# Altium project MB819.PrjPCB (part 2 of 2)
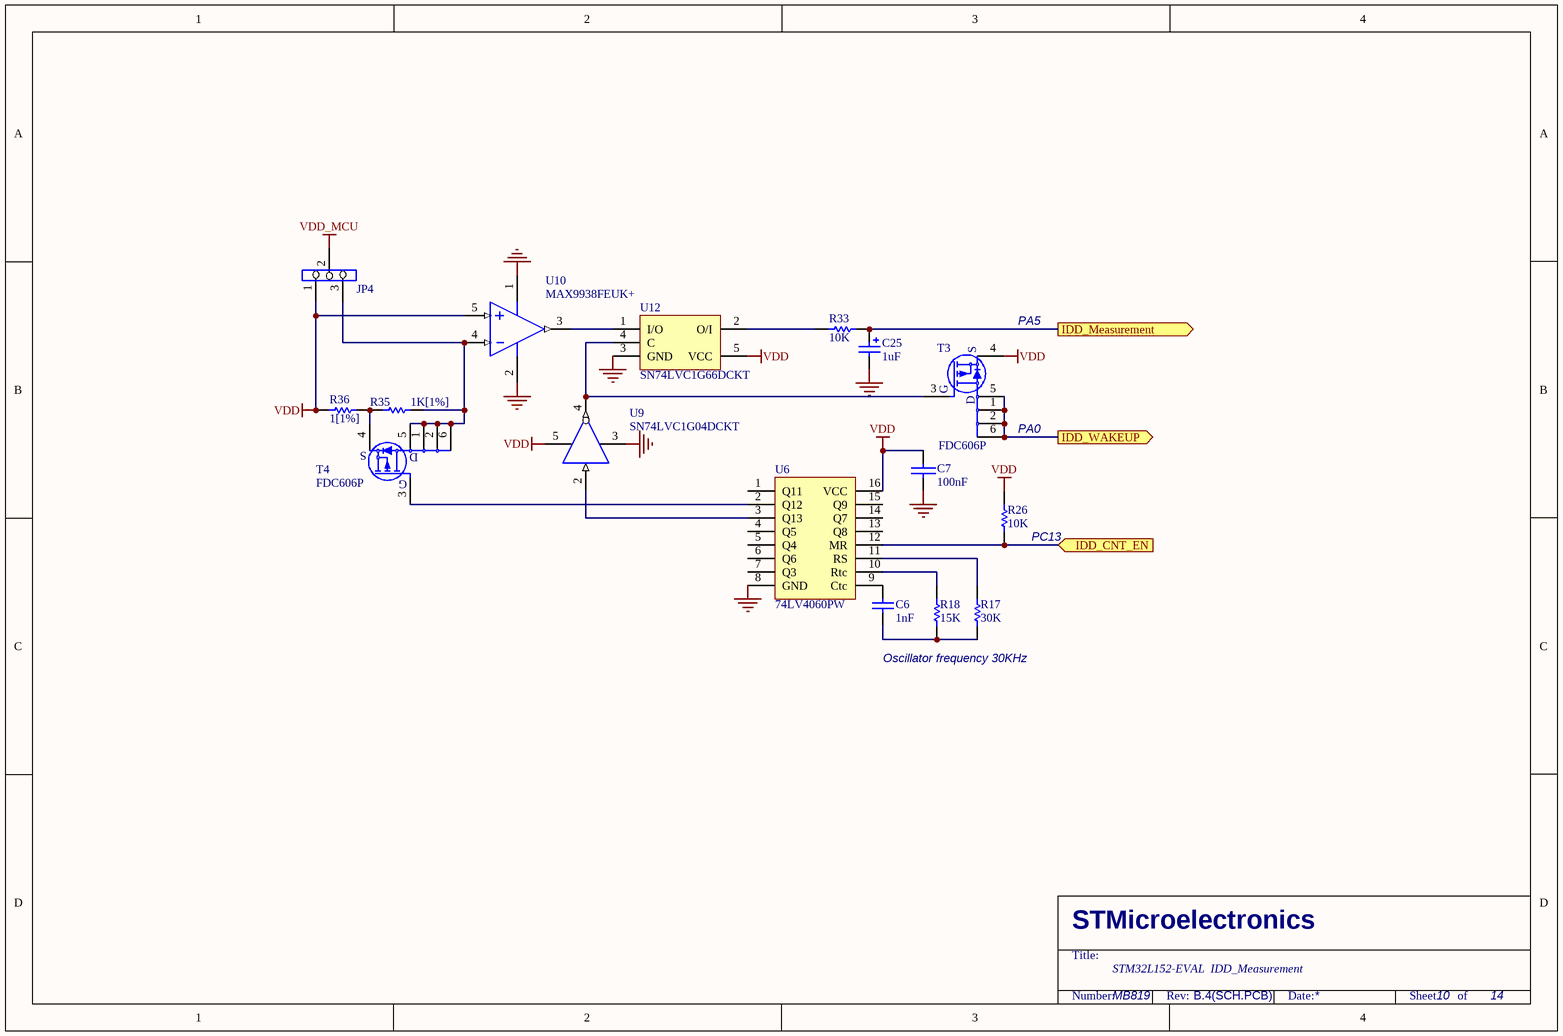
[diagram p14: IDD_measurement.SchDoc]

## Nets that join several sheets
+3V3: Audio (C66.1 R109.2 U27.6 U28.5), Extension connector (CN6.48), LCD_MicroSD (12 pins), Peripherals (8 pins), Power (5 pins), RS232_IrDA (16 pins), ST_LINK (15 pins), TemSensor (C41.2 R63.2 R66.2 U18.8)
+5V: LCD_MicroSD (CN14.13 CN14.14), Power (9 pins)
D5V: Extension connector (CN6.49 CN7.19), Power (JP12.3)
GND: Audio (14 pins), Extension connector (11 pins), JTAG&Trace (27 pins), LCD_MicroSD (19 pins), MCU (26 pins), Peripherals (25 pins), Power (16 pins), RS232_IrDA (29 pins), ST_LINK (25 pins), TemSensor (5 pins), Touch Sensing (C11.1 C18.2), IDD_measurement (7 pins)
PC8: Extension connector (CN6.4), MCU (U11.65), Touch Sensing (C18.1 R24.1)
U5V: MCU (R86.1), Peripherals (C5.1 CN1.1 U7.5), Power (JP12.5)
U5V_ST_LINK: Power (JP12.7), ST_LINK (CN11.1 R10.1)
VDD: Audio (R98.1 R99.2), JTAG&Trace (8 pins), LCD_MicroSD (14 pins), MCU (R137.2 SW1.1 SW2.1), Peripherals (12 pins), Power (JP13.2), RS232_IrDA (13 pins), ST_LINK (C49.1 R90.1 U19.8), TemSensor (5 pins), IDD_measurement (9 pins)
VDD_MCU: MCU (11 pins), IDD_measurement (JP4.2)
VLCD: Extension connector (CN6.31), MCU (C22.1 U11.6)
COM0: Extension connector (CN6.6), LCD_Glass (U20.20), MCU (U11.67)
COM1: Extension connector (CN6.7), LCD_Glass (U20.19), MCU (U11.68)
COM2: Extension connector (CN6.8), LCD_Glass (U20.18), MCU (U11.69)
COM3: Extension connector (CN6.46), LCD_Glass (U20.17), MCU (U11.96)
NetC25_1: Peripherals (JP14.2), IDD_measurement (C25.1 R33.2)
NetCN4_10: LCD_MicroSD (CN4.10), MCU (JP2.1)
NetD2_2: MCU (D2.2), RS232_IrDA (JP9.3)
NetJP7_3: MCU (JP7.3), RS232_IrDA (R44.1 U3.2 U3.3)
NetJP8_3: MCU (JP8.3), RS232_IrDA (R11.1)
NetJP10_1: MCU (JP10.1), Peripherals (R96.2)
NetJP11_2: MCU (JP11.2), TemSensor (R61.2)
NetJP18_1: MCU (JP18.1), Peripherals (R124.1)
NetJP19_1: MCU (JP19.1), Peripherals (R122.1)
NetR138_2: MCU (R138.2), RS232_IrDA (U8.20)
PA0: Extension connector (CN6.9), MCU (U11.23), Peripherals (R120.2), IDD_measurement (T3.1 T3.2 T3.5 T3.6)
PA1: Extension connector (CN7.44), LCD_Glass (U20.15), MCU (U11.24)
PA2: Extension connector (CN7.43), LCD_Glass (U20.16), MCU (U11.25)
PA3: Extension connector (CN7.42), LCD_Glass (U20.21), MCU (U11.26)
PA4: Audio (R103.1), Extension connector (CN7.41), MCU (U11.29)
PA5: Extension connector (CN7.40), MCU (U11.30), Peripherals (R45.1)
PA6: Extension connector (CN7.38), LCD_Glass (U20.22), MCU (U11.31)
PA7: Extension connector (CN7.37), LCD_Glass (U20.13), MCU (U11.32)
PA11: Extension connector (CN6.12), MCU (U11.70), Peripherals (R16.1)
PA12: Extension connector (CN6.13), MCU (U11.71), Peripherals (R25.1)
PA13: Extension connector (CN6.14), JTAG&Trace (D4.3 RS1.3), MCU (U11.72), ST_LINK (U19.7 U23.27)
PA14: Extension connector (CN6.16), JTAG&Trace (D3.3 RS1.5), MCU (U11.76), ST_LINK (U23.15 U23.26)
PA15: Extension connector (CN6.20), JTAG&Trace (D5.3 RS1.9), MCU (U11.77), ST_LINK (U23.17)
PB0: Extension connector (CN7.34), LCD_Glass (U20.14), MCU (U11.35)
PB1: Extension connector (CN7.33), LCD_Glass (U20.23), MCU (U11.36)
PB2: Extension connector (CN7.32), MCU (R43.1 U11.37), Touch Sensing (R22.2 R23.2 R24.2)
PB3: Extension connector (CN6.33), JTAG&Trace (D6.3 RS1.7), MCU (U11.89), Peripherals (JP17.4), ST_LINK (U19.6)
PB4: Extension connector (CN6.34), MCU (JP10.2 U11.90)
PB5: Extension connector (CN6.35), MCU (JP11.1 U11.91), Peripherals (JP17.2)
PB6: Extension connector (CN6.36), MCU (U11.92), TemSensor (R69.1)
PB7: Extension connector (CN6.37), MCU (U11.93), TemSensor (R62.1)
PB8: Extension connector (CN6.45), LCD_Glass (U20.12), MCU (U11.95)
PB10: Extension connector (CN7.18), LCD_Glass (U20.24), MCU (U11.47)
PB11: Extension connector (CN7.17), LCD_Glass (U20.11), MCU (U11.48)
PB12: Extension connector (CN7.16), MCU (U11.51), Peripherals (JP17.6)
PB13: Extension connector (CN7.15), LCD_MicroSD (U14.3), MCU (U11.52)
PB14: Extension connector (CN7.14), LCD_MicroSD (R58.1), MCU (U11.53)
PB15: Extension connector (CN7.13), LCD_MicroSD (U15.3), MCU (U11.54)
PC0: Extension connector (CN7.48), LCD_Glass (U20.25), MCU (U11.15)
PC1: Extension connector (CN7.47), LCD_Glass (U20.26), MCU (U11.16)
PC2: Extension connector (CN7.46), LCD_Glass (U20.9), MCU (U11.17)
PC3: Extension connector (CN7.45), LCD_Glass (U20.10), MCU (U11.18)
PC4: Extension connector (CN7.36), LCD_Glass (U20.27), MCU (U11.33)
PC5: Extension connector (CN7.35), LCD_Glass (U20.28), MCU (U11.34)
PC6: Extension connector (R30.1), MCU (U11.63), Touch Sensing (R14.1 R23.1)
PC7: Extension connector (R28.2), MCU (U11.64), Touch Sensing (R13.1 R22.1)
PC9: Extension connector (CN6.5), MCU (U11.66), Touch Sensing (R29.1)
PC10: Extension connector (CN6.17), MCU (JP7.2 U11.78)
PC11: Extension connector (CN6.18), MCU (JP8.2 U11.79)
PC12: Extension connector (CN6.21), LCD_Glass (U20.35), MCU (U11.80)
PC13: Extension connector (CN7.49 R31.1), MCU (U11.7), IDD_measurement (R26.2 U6.12)
PC14: Extension connector (SB1.1), MCU (R37.2 U11.8)
PC15: Extension connector (SB4.1), MCU (R38.2 U11.9)
PD0: Extension connector (CN6.22), MCU (U11.81), Peripherals (R111.1)
PD1: Extension connector (CN6.23), MCU (U11.82), Peripherals (R125.1)
PD2: Extension connector (CN6.24), LCD_Glass (U20.36), MCU (U11.83)
PD3: Extension connector (CN6.25), MCU (U11.84), RS232_IrDA (JP9.1)
PD4: Extension connector (CN6.26), MCU (JP18.2 U11.85), RS232_IrDA (R12.1 U4.2)
PD5: Extension connector (CN6.27), MCU (JP19.2 U11.86), RS232_IrDA (R21.1 U4.3)
PD6: Extension connector (CN6.28), MCU (U11.87), RS232_IrDA (R19.1)
PD7: Extension connector (CN6.29), LCD_MicroSD (R59.2 U13.2), MCU (U11.88)
PD8: Extension connector (CN7.12), LCD_Glass (U20.7), MCU (U11.55)
PD9: Extension connector (CN7.8), LCD_Glass (U20.8), MCU (U11.56)
PD10: Extension connector (CN7.7), LCD_Glass (U20.29), MCU (U11.57)
PD11: Extension connector (CN7.6), LCD_Glass (U20.30), MCU (U11.58)
PD12: Extension connector (CN7.5), LCD_Glass (U20.5), MCU (U11.59)
PD13: Extension connector (CN7.4), LCD_Glass (U20.6), MCU (U11.60)
PD14: Extension connector (CN7.3), LCD_Glass (U20.31), MCU (U11.61)
PD15: Extension connector (CN7.2), LCD_Glass (U20.32), MCU (U11.62)
PE0: Extension connector (CN6.38), LCD_Glass (U20.3), MCU (U11.97)
PE1: Extension connector (CN6.40), LCD_Glass (U20.4), MCU (U11.98)
PE2: Extension connector (CN6.41), JTAG&Trace (CN8.12), MCU (R77.1 U11.1)
PE3: Extension connector (CN6.42), JTAG&Trace (R70.2), MCU (R78.1 U11.2)
PE4: Extension connector (CN6.43), JTAG&Trace (R71.2), MCU (U11.3)
PE5: Extension connector (CN6.44), JTAG&Trace (CN8.18), MCU (R88.1 U11.4)
PE6: Extension connector (CN6.47), JTAG&Trace (CN8.20), MCU (JP2.2 U11.5)
PE7: Audio (R75.1), Extension connector (CN7.31), MCU (U11.38)
PE8: Extension connector (CN7.29), MCU (U11.39), Peripherals (R112.2)
PE9: Extension connector (CN7.28), MCU (U11.40), Peripherals (R126.2)
PE10: Extension connector (CN7.27), MCU (U11.41), Peripherals (R127.2)
PE11: Extension connector (CN7.26), MCU (U11.42), Peripherals (R117.2)
PE12: Extension connector (CN7.25), MCU (U11.43), Peripherals (R118.2)
PE13: Extension connector (CN7.22), LCD_MicroSD (U14.2), MCU (U11.44)
PE14: Extension connector (CN7.21), LCD_MicroSD (R57.1), MCU (U11.45)
PE15: Extension connector (CN7.20), LCD_MicroSD (U15.2), MCU (U11.46)
PH0: Extension connector (SB3.1), MCU (C30.1 U11.12 X2.2)
PH1: Extension connector (SB2.1), MCU (R39.1 U11.13)
PH2: Extension connector (CN6.32), LCD_MicroSD (R64.2 U13.3), MCU (U11.73)
RESET#: Extension connector (R49.2), JTAG&Trace (D7.3 RS1.13), LCD_MicroSD (TR4.1), MCU (6 pins), ST_LINK (U23.18)
SEG38: LCD_Glass (U20.33), MCU (R77.2)
SEG39: LCD_Glass (U20.34), MCU (R78.2)
SEG40: LCD_Glass (U20.1), MCU (JP7.1)
SEG41: LCD_Glass (U20.2), MCU (JP8.1)
T_JRST: JTAG&Trace (D8.3 RS1.11), MCU (JP10.3), ST_LINK (U23.19)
